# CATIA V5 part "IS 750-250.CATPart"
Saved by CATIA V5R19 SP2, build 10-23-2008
Part number: IS 750-250
Bounding box of the stored display mesh (mm): x -24.865 to 24.865, y -24.997 to 24.997, z 0 to 595
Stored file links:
  C:\Users\Bora\Desktop\3D Katı model\IS serisi\IS 750\IS 750-250.CATPart
  C:\Program Files\Dassault Systemes\B19\intel_a\reffiles\standard\MetricThickPitch.txt
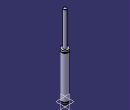
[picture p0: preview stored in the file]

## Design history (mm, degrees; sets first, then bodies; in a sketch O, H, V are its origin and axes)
Body1 (main body)
  Sketch1 on yz-plane, origin (0, 0, 0), H (0, 1, 0), V (0, 0, 1)
    point P1 (25, 329.5)
    point P2 (25, 325.5)
    point P5 (12.5, 594)
    point P7 (12.5, 594)
    point P12 (25, 325.5)
    point P13 (25, 329.5)
    arc A1 centre (25, 327.5) radius 2 from (25, 329.5) to (25, 325.5) ccw
    line L1 (25, 0) -> (25, 8)
    line L2 (12.5, 594) -> (12.5, 342)
    arc A2 centre (11.5, 594) radius 1 from (12.5, 594) to (11.5, 595) ccw
    line L3 (21.5, 13) -> (21.5, 8)
    line L4 (25, 13) -> (25, 325.5)
    line L5 (25, 329.5) -> (25, 342)
    line L6 (11.5, 595) -> (0, 595)
    point P15 (0, 595)
    line L7 (12.5, 342) -> (25, 342)
    line L8 (0, 0) -> (25, 0)
    line L9 (21.5, 13) -> (25, 13)
    line L10 (21.5, 8) -> (25, 8)
    coincidence: P15 V, P1 P13, P2 P12, P5 P7
    tangency: L6 A2
    horizontal: L7 H, L8 H, L9 H, L10 H
  Shaft1: profile Sketch1, axis Sketch1.V, angle 360
  Sketch2 on face of Shaft1 from Sketch1.L8, origin (0, 0, 0), H (1, 0, 0), V (0, -1, 0)
    point P1 (10, 0)
    distance P1 V = 10
  Hole1: placed by Sketch2, at (10, 0, 0) direction (0, 0, 1), diameter 6.647, depth 13, threaded "M8", thread diameter 8, thread depth 13, pitch 1.25
  Sketch3 on face of Shaft1 from Sketch1.L8, origin (0, 0, 0), H (1, 0, 0), V (0, -1, 0)
    point P1 (-10, 0)
    distance P1 V = 10
  Hole2: placed by Sketch3, at (-10, 0, 0) direction (0, 0, 1), diameter 6.647, depth 13, threaded "M8", thread diameter 8, thread depth 13, pitch 1.25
